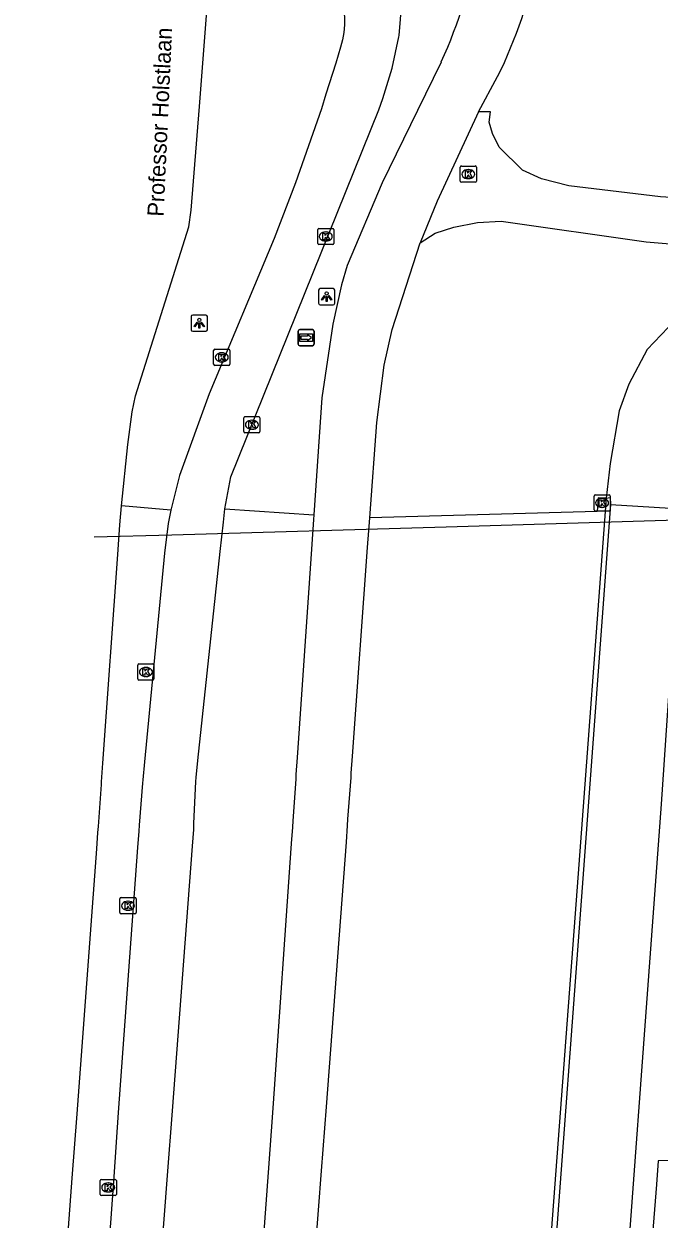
# Model space of a CAD drawing. Extents: x 160203 to 161526, y 379529 to 381797.
# Drawn here: x 160208 to 160247.2, y 379606.7 to 379680.5 of the extents above; entities that cross this region are included whole.
import ezdxf

# ---------------------------------------------------------------- set-up
doc = ezdxf.new("R2010")
doc.units = 0
for name, color, linetype in [('IMGEO_Berm_groen', 7, 'Continuous'), ('IMGEO_Berm_open', 7, 'Continuous'), ('IMGEO_Fietspad_gesloten', 7, 'Continuous'), ('IMGEO_Geluidsscherm', 7, 'Continuous'), ('IMGEO_Grasland_overig', 7, 'Continuous'), ('IMGEO_Groenvoorziening', 7, 'Continuous'), ('IMGEO_Kolk', 7, 'Continuous'), ('IMGEO_Lichtpunt', 7, 'Continuous'), ('IMGEO_Openbare_ruimte_label', 7, 'Continuous'), ('IMGEO_Rijbaan_autosnelweg', 7, 'Continuous'), ('IMGEO_Rijbaan_regionaal_gesloten', 7, 'Continuous'), ('IMGEO_Terreindeel_gesloten', 7, 'Continuous'), ('IMGEO_Terreindeel_open', 7, 'Continuous'), ('IMGEO_Wegwijzer', 7, 'Continuous')]:
    doc.layers.add(name, color=color, linetype=linetype)

msp = doc.modelspace()

# ---------------------------------------------------------------- linework, layer by layer
at = {"layer": 'IMGEO_Berm_groen'}
for points in [[(160390.225, 379666.417), (160378.918, 379665.49), (160370.461, 379664.989), (160352.999, 379664.981), (160339.851, 379664.575), (160325.385, 379664.316), (160308.074, 379664.328), (160292.518, 379664.538), (160278.805, 379664.805), (160267.431, 379664.675), (160258.969, 379664.633), (160255.777, 379664.543), (160253.164, 379664.378), (160251.015, 379663.778), (160249.088, 379662.862), (160247.801, 379661.732), (160246.517, 379660.362), (160245.38, 379658.236), (160244.777, 379656.594), (160244.23, 379653.335), (160243.981, 379651.198)], [(160243.981, 379651.198), (160244.216, 379651.233), (160244.239, 379650.815)], [(160244.239, 379650.815), (160248.617, 379650.528)]]:
    msp.add_lwpolyline(points, dxfattribs=at)
at = {"layer": 'IMGEO_Berm_open'}
for points in [[(160217.101, 379650.451), (160214.055, 379650.718)], [(160220.438, 379650.535), (160225.932, 379650.167)]]:
    msp.add_lwpolyline(points, dxfattribs=at)
at = {"layer": 'IMGEO_Fietspad_gesloten'}
for points in [[(160233.804, 379678.104), (160232.326, 379675.107), (160230.157, 379670.66), (160227.998, 379665.554), (160227.638, 379664.367), (160227.115, 379661.928), (160226.429, 379657.385), (160225.932, 379650.167)], [(160236.103, 379675.038), (160237.279, 379677.201)], [(160236.103, 379675.038), (160233.537, 379669.518), (160232.495, 379666.954)], [(160229.388, 379649.982), (160229.82, 379655.859), (160230.281, 379659.405), (160230.775, 379661.61), (160232.495, 379666.954)], [(160225.932, 379650.167), (160225.913, 379649.883), (160225.787, 379648.052), (160224.905, 379635.187), (160224.834, 379634.15), (160224.815, 379633.869), (160224.638, 379631.293), (160224.612, 379630.909), (160224.542, 379629.888), (160223.398, 379613.554), (160223.12, 379609.597), (160221.927, 379593.408), (160221.852, 379592.45), (160221.824, 379592.092), (160221.617, 379589.456), (160221.592, 379589.14), (160221.5, 379587.96), (160220.499, 379575.207), (160220.319, 379572.604), (160220.373, 379571.446)], [(160224.015, 379569.839), (160223.978, 379572.685), (160224.141, 379575.314), (160224.934, 379588.057), (160225.007, 379589.234), (160225.027, 379589.557), (160225.191, 379592.191), (160225.213, 379592.547), (160225.272, 379593.498), (160225.675, 379599.983), (160226.412, 379609.692), (160226.713, 379613.647), (160227.942, 379629.982), (160228.015, 379630.994), (160228.043, 379631.386), (160228.229, 379633.959), (160228.248, 379634.224), (160228.324, 379635.28), (160229.253, 379648.148), (160229.388, 379649.982)]]:
    msp.add_lwpolyline(points, dxfattribs=at)
for centre, radius, start, end in [((160199.552, 379693.414), 37.517, 335.91652, 348.03698), ((160207.983, 379691.447), 32.577, 334.06774, 347.75546)]:
    msp.add_arc(centre, radius, start, end, dxfattribs=at)
at = {"layer": 'IMGEO_Geluidsscherm'}
msp.add_lwpolyline([(160212.377, 379648.803), (160217.179, 379648.931), (160234.109, 379649.427), (160253.116, 379650.003)], dxfattribs=at)
at = {"layer": 'IMGEO_Grasland_overig'}
for points in [[(160250.231, 379669.61), (160247.336, 379669.791), (160241.681, 379670.475), (160239.981, 379670.898), (160238.818, 379671.425), (160237.368, 379672.848), (160236.96, 379673.703), (160236.754, 379674.399), (160236.841, 379675.025), (160236.103, 379675.038)], [(160232.495, 379666.954), (160233.427, 379667.542), (160234.581, 379667.912), (160236.035, 379668.205), (160237.492, 379668.279), (160246.445, 379667.009), (160251.637, 379666.58), (160263.798, 379665.879), (160289.607, 379665.409), (160317.066, 379665.574), (160328.462, 379665.484), (160366.057, 379665.966), (160397.352, 379667.764), (160409.9, 379668.264), (160437.173, 379669.126), (160442.8, 379669.22), (160460.825, 379668.755)]]:
    msp.add_lwpolyline(points, dxfattribs=at)
at = {"layer": 'IMGEO_Groenvoorziening'}
for points in [[(160243.981, 379651.198), (160243.477, 379651.217), (160243.413, 379650.38), (160229.388, 379649.982)], [(160243.981, 379651.198), (160242.191, 379627.227), (160240.385, 379603.16), (160239.216, 379587.326), (160238.124, 379573.068), (160238.446, 379573.061)]]:
    msp.add_lwpolyline(points, dxfattribs=at)
at = {"layer": 'IMGEO_Kolk'}
for p, q in [((160234.969, 379670.762), (160234.969, 379671.614)), ((160235.044, 379671.688), (160235.896, 379671.688)), ((160235.97, 379671.614), (160235.97, 379670.762)), ((160235.48, 379670.908), (160235.455, 379670.908)), ((160235.457, 379671.468), (160235.482, 379671.468)), ((160235.896, 379670.688), (160235.044, 379670.688)), ((160226.249, 379667.842), (160227.101, 379667.842)), ((160226.174, 379666.916), (160226.174, 379667.768)), ((160226.685, 379667.062), (160226.66, 379667.062)), ((160226.662, 379667.622), (160226.687, 379667.622)), ((160227.175, 379667.768), (160227.175, 379666.916)), ((160227.101, 379666.842), (160226.249, 379666.842)), ((160219.751, 379659.458), (160219.751, 379660.31)), ((160219.826, 379660.384), (160220.678, 379660.384)), ((160220.239, 379660.164), (160220.264, 379660.164)), ((160220.752, 379660.31), (160220.752, 379659.458)), ((160220.678, 379659.384), (160219.826, 379659.384)), ((160220.262, 379659.604), (160220.237, 379659.604)), ((160221.611, 379655.299), (160221.611, 379656.151)), ((160221.686, 379656.225), (160222.538, 379656.225)), ((160222.099, 379656.005), (160222.124, 379656.005)), ((160222.612, 379656.151), (160222.612, 379655.299)), ((160222.122, 379655.445), (160222.097, 379655.445)), ((160222.538, 379655.225), (160221.686, 379655.225)), ((160243.229, 379650.477), (160243.229, 379651.329)), ((160243.304, 379651.403), (160244.156, 379651.403)), ((160243.717, 379651.183), (160243.742, 379651.183)), ((160244.23, 379651.329), (160244.23, 379650.477)), ((160244.156, 379650.403), (160243.304, 379650.403)), ((160243.74, 379650.623), (160243.715, 379650.623)), ((160215.069, 379640.044), (160215.069, 379640.896)), ((160215.144, 379640.97), (160215.996, 379640.97)), ((160215.557, 379640.75), (160215.582, 379640.75)), ((160216.07, 379640.896), (160216.07, 379640.044)), ((160215.996, 379639.97), (160215.144, 379639.97)), ((160215.58, 379640.19), (160215.555, 379640.19)), ((160214.039, 379626.551), (160214.891, 379626.551)), ((160213.964, 379625.625), (160213.964, 379626.477)), ((160214.475, 379625.771), (160214.45, 379625.771)), ((160214.452, 379626.331), (160214.477, 379626.331)), ((160214.965, 379626.477), (160214.965, 379625.625)), ((160214.891, 379625.551), (160214.039, 379625.551)), ((160212.746, 379608.245), (160212.746, 379609.097)), ((160212.821, 379609.171), (160213.673, 379609.171)), ((160213.234, 379608.951), (160213.259, 379608.951)), ((160213.747, 379609.097), (160213.747, 379608.245)), ((160213.673, 379608.171), (160212.821, 379608.171)), ((160213.257, 379608.391), (160213.232, 379608.391))]:
    msp.add_line(p, q, dxfattribs=at)
for points in [[(160234.969, 379670.762), (160234.969, 379671.614)], [(160235.044, 379671.688), (160235.896, 379671.688)], [(160235.97, 379671.614), (160235.97, 379670.762)], [(160235.29, 379671.388), (160235.413, 379671.388), (160235.413, 379671.237), (160235.543, 379671.388), (160235.707, 379671.388), (160235.561, 379671.237), (160235.714, 379670.988), (160235.562, 379670.988), (160235.477, 379671.152), (160235.413, 379671.085), (160235.413, 379670.988), (160235.29, 379670.988), (160235.29, 379671.388)], [(160235.896, 379670.688), (160235.044, 379670.688)], [(160226.249, 379667.842), (160227.101, 379667.842)], [(160226.174, 379666.916), (160226.174, 379667.768)], [(160226.495, 379667.542), (160226.618, 379667.542), (160226.618, 379667.391), (160226.748, 379667.542), (160226.912, 379667.542), (160226.766, 379667.391), (160226.919, 379667.142), (160226.767, 379667.142), (160226.682, 379667.306), (160226.618, 379667.239), (160226.618, 379667.142), (160226.495, 379667.142), (160226.495, 379667.542)], [(160227.175, 379667.768), (160227.175, 379666.916)], [(160227.101, 379666.842), (160226.249, 379666.842)], [(160219.751, 379659.458), (160219.751, 379660.31)], [(160219.826, 379660.384), (160220.678, 379660.384)], [(160220.072, 379660.084), (160220.195, 379660.084), (160220.195, 379659.933), (160220.325, 379660.084), (160220.489, 379660.084), (160220.343, 379659.933), (160220.496, 379659.684), (160220.344, 379659.684), (160220.259, 379659.848), (160220.195, 379659.781), (160220.195, 379659.684), (160220.072, 379659.684), (160220.072, 379660.084)], [(160220.752, 379660.31), (160220.752, 379659.458)], [(160220.678, 379659.384), (160219.826, 379659.384)], [(160221.611, 379655.299), (160221.611, 379656.151)], [(160221.686, 379656.225), (160222.538, 379656.225)], [(160222.612, 379656.151), (160222.612, 379655.299)], [(160221.932, 379655.925), (160222.055, 379655.925), (160222.055, 379655.774), (160222.185, 379655.925), (160222.349, 379655.925), (160222.203, 379655.774), (160222.356, 379655.525), (160222.204, 379655.525), (160222.119, 379655.689), (160222.055, 379655.622), (160222.055, 379655.525), (160221.932, 379655.525), (160221.932, 379655.925)], [(160222.538, 379655.225), (160221.686, 379655.225)], [(160243.229, 379650.477), (160243.229, 379651.329)], [(160243.304, 379651.403), (160244.156, 379651.403)], [(160243.55, 379651.103), (160243.673, 379651.103), (160243.673, 379650.952), (160243.803, 379651.103), (160243.967, 379651.103), (160243.821, 379650.952), (160243.974, 379650.703), (160243.822, 379650.703), (160243.737, 379650.867), (160243.673, 379650.8), (160243.673, 379650.703), (160243.55, 379650.703), (160243.55, 379651.103)], [(160244.23, 379651.329), (160244.23, 379650.477)], [(160244.156, 379650.403), (160243.304, 379650.403)], [(160215.069, 379640.044), (160215.069, 379640.896)], [(160215.144, 379640.97), (160215.996, 379640.97)], [(160215.39, 379640.67), (160215.513, 379640.67), (160215.513, 379640.519), (160215.643, 379640.67), (160215.807, 379640.67), (160215.661, 379640.519), (160215.814, 379640.27), (160215.662, 379640.27), (160215.577, 379640.434), (160215.513, 379640.367), (160215.513, 379640.27), (160215.39, 379640.27), (160215.39, 379640.67)], [(160216.07, 379640.896), (160216.07, 379640.044)], [(160215.996, 379639.97), (160215.144, 379639.97)], [(160214.039, 379626.551), (160214.891, 379626.551)], [(160213.964, 379625.625), (160213.964, 379626.477)], [(160214.285, 379626.251), (160214.408, 379626.251), (160214.408, 379626.1), (160214.538, 379626.251), (160214.702, 379626.251), (160214.556, 379626.1), (160214.709, 379625.851), (160214.557, 379625.851), (160214.472, 379626.015), (160214.408, 379625.948), (160214.408, 379625.851), (160214.285, 379625.851), (160214.285, 379626.251)], [(160214.965, 379626.477), (160214.965, 379625.625)], [(160214.891, 379625.551), (160214.039, 379625.551)], [(160212.746, 379608.245), (160212.746, 379609.097)], [(160212.821, 379609.171), (160213.673, 379609.171)], [(160213.067, 379608.871), (160213.19, 379608.871), (160213.19, 379608.72), (160213.32, 379608.871), (160213.484, 379608.871), (160213.338, 379608.72), (160213.491, 379608.471), (160213.339, 379608.471), (160213.254, 379608.635), (160213.19, 379608.568), (160213.19, 379608.471), (160213.067, 379608.471), (160213.067, 379608.871)], [(160213.747, 379609.097), (160213.747, 379608.245)], [(160213.673, 379608.171), (160212.821, 379608.171)]]:
    msp.add_lwpolyline(points, dxfattribs=at)
for centre, start, end in [((160235.046, 379671.612), 91.55205, 178.44795), ((160235.046, 379671.612), 91.55205, 178.44795), ((160235.894, 379671.612), 1.55205, 88.44795), ((160235.894, 379671.612), 1.55205, 88.44795), ((160235.046, 379670.764), 181.55205, 268.44795), ((160235.046, 379670.764), 181.55205, 268.44795), ((160235.894, 379670.764), 271.55205, 358.44795), ((160235.894, 379670.764), 271.55205, 358.44795), ((160226.251, 379667.766), 91.55205, 178.44795), ((160226.251, 379667.766), 91.55205, 178.44795), ((160227.099, 379667.766), 1.55205, 88.44795), ((160227.099, 379667.766), 1.55205, 88.44795), ((160226.251, 379666.918), 181.55205, 268.44795), ((160226.251, 379666.918), 181.55205, 268.44795), ((160227.099, 379666.918), 271.55205, 358.44795), ((160227.099, 379666.918), 271.55205, 358.44795), ((160219.828, 379660.308), 91.55205, 178.44795), ((160219.828, 379660.308), 91.55205, 178.44795), ((160220.676, 379660.308), 1.55205, 88.44795), ((160220.676, 379660.308), 1.55205, 88.44795), ((160219.828, 379659.46), 181.55205, 268.44795), ((160219.828, 379659.46), 181.55205, 268.44795), ((160220.676, 379659.46), 271.55205, 358.44795), ((160220.676, 379659.46), 271.55205, 358.44795), ((160221.688, 379656.149), 91.55205, 178.44795), ((160221.688, 379656.149), 91.55205, 178.44795), ((160222.536, 379656.149), 1.55205, 88.44795), ((160222.536, 379656.149), 1.55205, 88.44795), ((160221.688, 379655.301), 181.55205, 268.44795), ((160221.688, 379655.301), 181.55205, 268.44795), ((160222.536, 379655.301), 271.55205, 358.44795), ((160222.536, 379655.301), 271.55205, 358.44795), ((160243.306, 379651.327), 91.55205, 178.44795), ((160243.306, 379651.327), 91.55205, 178.44795), ((160244.154, 379651.327), 1.55205, 88.44795), ((160244.154, 379651.327), 1.55205, 88.44795), ((160243.306, 379650.479), 181.55205, 268.44795), ((160243.306, 379650.479), 181.55205, 268.44795), ((160244.154, 379650.479), 271.55205, 358.44795), ((160244.154, 379650.479), 271.55205, 358.44795), ((160215.146, 379640.894), 91.55205, 178.44795), ((160215.146, 379640.894), 91.55205, 178.44795), ((160215.994, 379640.894), 1.55205, 88.44795), ((160215.994, 379640.894), 1.55205, 88.44795), ((160215.146, 379640.046), 181.55205, 268.44795), ((160215.146, 379640.046), 181.55205, 268.44795), ((160215.994, 379640.046), 271.55205, 358.44795), ((160215.994, 379640.046), 271.55205, 358.44795), ((160214.041, 379626.475), 91.55205, 178.44795), ((160214.041, 379626.475), 91.55205, 178.44795), ((160214.889, 379626.475), 1.55205, 88.44795), ((160214.889, 379626.475), 1.55205, 88.44795), ((160214.041, 379625.627), 181.55205, 268.44795), ((160214.041, 379625.627), 181.55205, 268.44795), ((160214.889, 379625.627), 271.55205, 358.44795), ((160214.889, 379625.627), 271.55205, 358.44795), ((160212.823, 379609.095), 91.55205, 178.44795), ((160212.823, 379609.095), 91.55205, 178.44795), ((160213.671, 379609.095), 1.55205, 88.44795), ((160213.671, 379609.095), 1.55205, 88.44795), ((160212.823, 379608.247), 181.55205, 268.44795), ((160212.823, 379608.247), 181.55205, 268.44795), ((160213.671, 379608.247), 271.55205, 358.44795), ((160213.671, 379608.247), 271.55205, 358.44795)]:
    msp.add_arc(centre, 0.0765, start, end, dxfattribs=at)
for centre, major_axis, ratio, start_param, end_param in [((160235.456, 379671.188), (-0.387, 0.002), 0.722429, 4.712389, 7.853982), ((160235.481, 379671.188), (-0.39, 0.002), 0.717154, 1.570796, 4.712389), ((160226.661, 379667.342), (-0.387, 0.002), 0.722429, 4.712389, 7.853982), ((160226.686, 379667.342), (-0.39, 0.002), 0.717154, 1.570796, 4.712389), ((160220.238, 379659.884), (-0.387, 0.002), 0.722429, 4.712389, 7.853982), ((160220.263, 379659.884), (-0.39, 0.002), 0.717154, 1.570796, 4.712389), ((160222.098, 379655.725), (-0.387, 0.002), 0.722429, 4.712389, 7.853982), ((160222.123, 379655.725), (-0.39, 0.002), 0.717154, 1.570796, 4.712389), ((160243.716, 379650.903), (-0.387, 0.002), 0.722429, 4.712389, 7.853982), ((160243.741, 379650.903), (-0.39, 0.002), 0.717154, 1.570796, 4.712389), ((160215.556, 379640.47), (-0.387, 0.002), 0.722429, 4.712389, 7.853982), ((160215.581, 379640.47), (-0.39, 0.002), 0.717154, 1.570796, 4.712389), ((160214.451, 379626.051), (-0.387, 0.002), 0.722429, 4.712389, 7.853982), ((160214.476, 379626.051), (-0.39, 0.002), 0.717154, 1.570796, 4.712389), ((160213.233, 379608.671), (-0.387, 0.002), 0.722429, 4.712389, 7.853982), ((160213.258, 379608.671), (-0.39, 0.002), 0.717154, 1.570796, 4.712389)]:
    msp.add_ellipse(centre, major_axis=major_axis, ratio=ratio, start_param=start_param, end_param=end_param, dxfattribs=at)
at = {"layer": 'IMGEO_Lichtpunt'}
for p, q in [((160227.13, 379664.123), (160226.322, 379664.123)), ((160227.13, 379664.123), (160226.322, 379664.123)), ((160226.228, 379664.028), (160226.228, 379663.221)), ((160226.228, 379664.028), (160226.228, 379663.221)), ((160227.224, 379663.221), (160227.224, 379664.028)), ((160227.224, 379663.221), (160227.224, 379664.028)), ((160226.322, 379663.127), (160227.13, 379663.127)), ((160226.322, 379663.127), (160227.13, 379663.127)), ((160218.367, 379662.395), (160218.367, 379661.588)), ((160218.367, 379662.395), (160218.367, 379661.588)), ((160219.269, 379662.49), (160218.461, 379662.49)), ((160219.269, 379662.49), (160218.461, 379662.49)), ((160219.363, 379661.588), (160219.363, 379662.395)), ((160219.363, 379661.588), (160219.363, 379662.395)), ((160218.461, 379661.494), (160219.269, 379661.494)), ((160218.461, 379661.494), (160219.269, 379661.494))]:
    msp.add_line(p, q, dxfattribs=at)
for points in [[(160226.602, 379663.692), (160226.641, 379663.664), (160226.453, 379663.402), (160226.415, 379663.429), (160226.602, 379663.692)], [(160226.704, 379663.644), (160226.751, 379663.644), (160226.751, 379663.322), (160226.704, 379663.322), (160226.704, 379663.644)], [(160226.814, 379663.664), (160226.852, 379663.691), (160227.039, 379663.429), (160227, 379663.401), (160226.814, 379663.664)], [(160218.741, 379662.059), (160218.78, 379662.031), (160218.592, 379661.769), (160218.554, 379661.796), (160218.741, 379662.059)], [(160218.843, 379662.011), (160218.89, 379662.011), (160218.89, 379661.689), (160218.843, 379661.689), (160218.843, 379662.011)], [(160218.953, 379662.031), (160218.991, 379662.058), (160219.178, 379661.796), (160219.139, 379661.768), (160218.953, 379662.031)]]:
    msp.add_lwpolyline(points, dxfattribs=at)
for centre in [(160226.727, 379663.826), (160218.866, 379662.193)]:
    msp.add_circle(centre, 0.0994, dxfattribs=at)
for centre, start, end in [((160226.322, 379664.028), 90, 180), ((160226.322, 379664.028), 90, 180), ((160227.13, 379664.028), 0, 90), ((160227.13, 379664.028), 0, 90), ((160226.322, 379663.221), 180, 270), ((160226.322, 379663.221), 180, 270), ((160227.13, 379663.221), 270, 0), ((160227.13, 379663.221), 270, 360), ((160218.461, 379662.395), 90, 180), ((160218.461, 379662.395), 90, 180), ((160219.269, 379662.395), 0, 90), ((160219.269, 379662.395), 0, 90), ((160218.461, 379661.588), 180, 270), ((160218.461, 379661.588), 180, 270), ((160219.269, 379661.588), 270, 0), ((160219.269, 379661.588), 270, 360)]:
    msp.add_arc(centre, 0.0946, start, end, dxfattribs=at)
at = {"layer": 'IMGEO_Rijbaan_autosnelweg'}
msp.add_lwpolyline([(160248.338, 379610.328), (160247.186, 379610.319), (160247.076, 379608.861), (160246.804, 379605.262), (160246.54, 379601.751), (160246.266, 379598.129), (160245.994, 379594.519), (160245.963, 379594.106), (160248.012, 379594.17)], dxfattribs=at)
at = {"layer": 'IMGEO_Rijbaan_regionaal_gesloten'}
for points in [[(160220.438, 379650.535), (160220.821, 379652.521), (160229.942, 379675.15), (160230.202, 379675.844), (160230.778, 379677.725), (160231.183, 379679.651), (160231.198, 379679.745), (160231.363, 379681.762), (160233.173, 379705.38), (160234.502, 379721.827), (160234.591, 379722.805)], [(160214.055, 379650.718), (160214.447, 379654.503), (160214.716, 379656.524), (160214.934, 379657.505), (160218.224, 379667.943), (160218.366, 379668.969), (160218.869, 379675.352), (160222.18, 379718.179)], [(160227.415, 379707.754), (160226.215, 379692.806), (160226.21, 379691.422), (160226.329, 379690.043), (160226.36, 379689.817), (160227.663, 379681.937), (160227.7, 379681.784), (160227.783, 379681.324), (160227.825, 379680.858), (160227.825, 379680.391), (160227.783, 379679.925), (160227.7, 379679.465), (160227.576, 379679.014), (160227.303, 379678.04), (160226.677, 379676.114), (160226.403, 379675.215), (160224.801, 379670.649), (160223.488, 379667.218), (160219.468, 379657.633), (160217.641, 379652.6), (160217.101, 379650.451)], [(160208.041, 379571.389), (160208.119, 379572.324), (160208.331, 379574.868), (160209.392, 379587.618), (160209.491, 379588.807), (160209.517, 379589.11), (160209.726, 379591.774), (160209.751, 379592.111), (160209.823, 379593.075), (160211.024, 379609.249), (160211.319, 379613.218), (160212.534, 379629.563), (160212.609, 379630.576), (160212.636, 379630.941), (160212.825, 379633.539), (160212.837, 379633.696), (160212.919, 379634.851), (160213.841, 379647.722), (160213.971, 379649.544), (160214.055, 379650.718)], [(160217.101, 379650.451), (160216.949, 379649.629), (160216.728, 379647.802), (160215.482, 379634.923), (160215.379, 379633.815), (160215.363, 379633.613), (160215.157, 379631.018), (160215.128, 379630.654), (160215.048, 379629.643), (160213.869, 379613.301), (160213.582, 379609.32), (160212.415, 379593.15), (160212.346, 379592.183), (160212.324, 379591.883), (160212.12, 379589.182), (160212.097, 379588.882), (160212.007, 379587.691), (160211.042, 379574.94), (160210.848, 379572.388), (160210.774, 379571.478)], [(160214.024, 379571.795), (160214.078, 379572.463), (160214.288, 379575.03), (160215.327, 379587.785), (160215.424, 379588.974), (160215.448, 379589.275), (160215.578, 379591.95), (160215.597, 379592.274), (160215.67, 379593.24), (160216.902, 379609.416), (160217.205, 379613.404), (160218.449, 379629.73), (160218.527, 379630.76), (160218.535, 379631.12), (160218.658, 379633.708), (160218.672, 379633.969), (160218.772, 379635.016), (160220.155, 379647.896), (160220.351, 379649.725), (160220.438, 379650.535)]]:
    msp.add_lwpolyline(points, dxfattribs=at)
at = {"layer": 'IMGEO_Terreindeel_gesloten'}
msp.add_lwpolyline([(160244.239, 379650.815), (160242.504, 379627.175), (160240.713, 379603.15), (160239.547, 379587.246), (160238.446, 379573.061)], dxfattribs=at)
at = {"layer": 'IMGEO_Terreindeel_open'}
msp.add_lwpolyline([(160242.455, 379573.148), (160244.497, 379593.006), (160247.398, 379632.321), (160248.617, 379650.528)], dxfattribs=at)
at = {"layer": 'IMGEO_Wegwijzer'}
for p, q in [((160224.961, 379660.698), (160224.961, 379661.498)), ((160224.961, 379661.498), (160224.961, 379660.698)), ((160225.061, 379661.598), (160225.851, 379661.598)), ((160225.851, 379661.598), (160225.061, 379661.598)), ((160225.951, 379661.498), (160225.951, 379660.698)), ((160225.951, 379660.698), (160225.951, 379661.498)), ((160225.851, 379660.598), (160225.061, 379660.598)), ((160225.061, 379660.598), (160225.851, 379660.598))]:
    msp.add_line(p, q, dxfattribs=at)
for points in [[(160225.062, 379661.33), (160225.85, 379661.33), (160225.85, 379660.866), (160225.062, 379660.866), (160225.062, 379661.33)], [(160225.127, 379661.182), (160225.127, 379661.098), (160225.127, 379661.014), (160225.538, 379661.014), (160225.538, 379660.931), (160225.785, 379661.098), (160225.538, 379661.265), (160225.538, 379661.182), (160225.127, 379661.182)]]:
    msp.add_lwpolyline(points, dxfattribs=at)
for centre, start, end in [((160225.061, 379661.498), 90, 180), ((160225.061, 379661.498), 90, 180), ((160225.851, 379661.498), 0, 90), ((160225.851, 379661.498), 360, 90), ((160225.061, 379660.698), 180, 270), ((160225.061, 379660.698), 180, 270), ((160225.851, 379660.698), 270, 0), ((160225.851, 379660.698), 270, 0)]:
    msp.add_arc(centre, 0.1, start, end, dxfattribs=at)

# ---------------------------------------------------------------- texts
at = {"layer": 'IMGEO_Openbare_ruimte_label'}
msp.add_text('Professor Holstlaan', height=1, rotation=87.36362, dxfattribs=at).set_placement((160216.657, 379668.55))

doc.saveas('drawing.dxf')
